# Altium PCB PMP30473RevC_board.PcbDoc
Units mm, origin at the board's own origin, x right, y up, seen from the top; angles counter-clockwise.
Board outline 38.1 x 50.8 mm, 2 copper layers (Top Layer, Bottom Layer), stack 1.575 mm thick; 60 components, 22 nets, 134 pads, 14 vias.
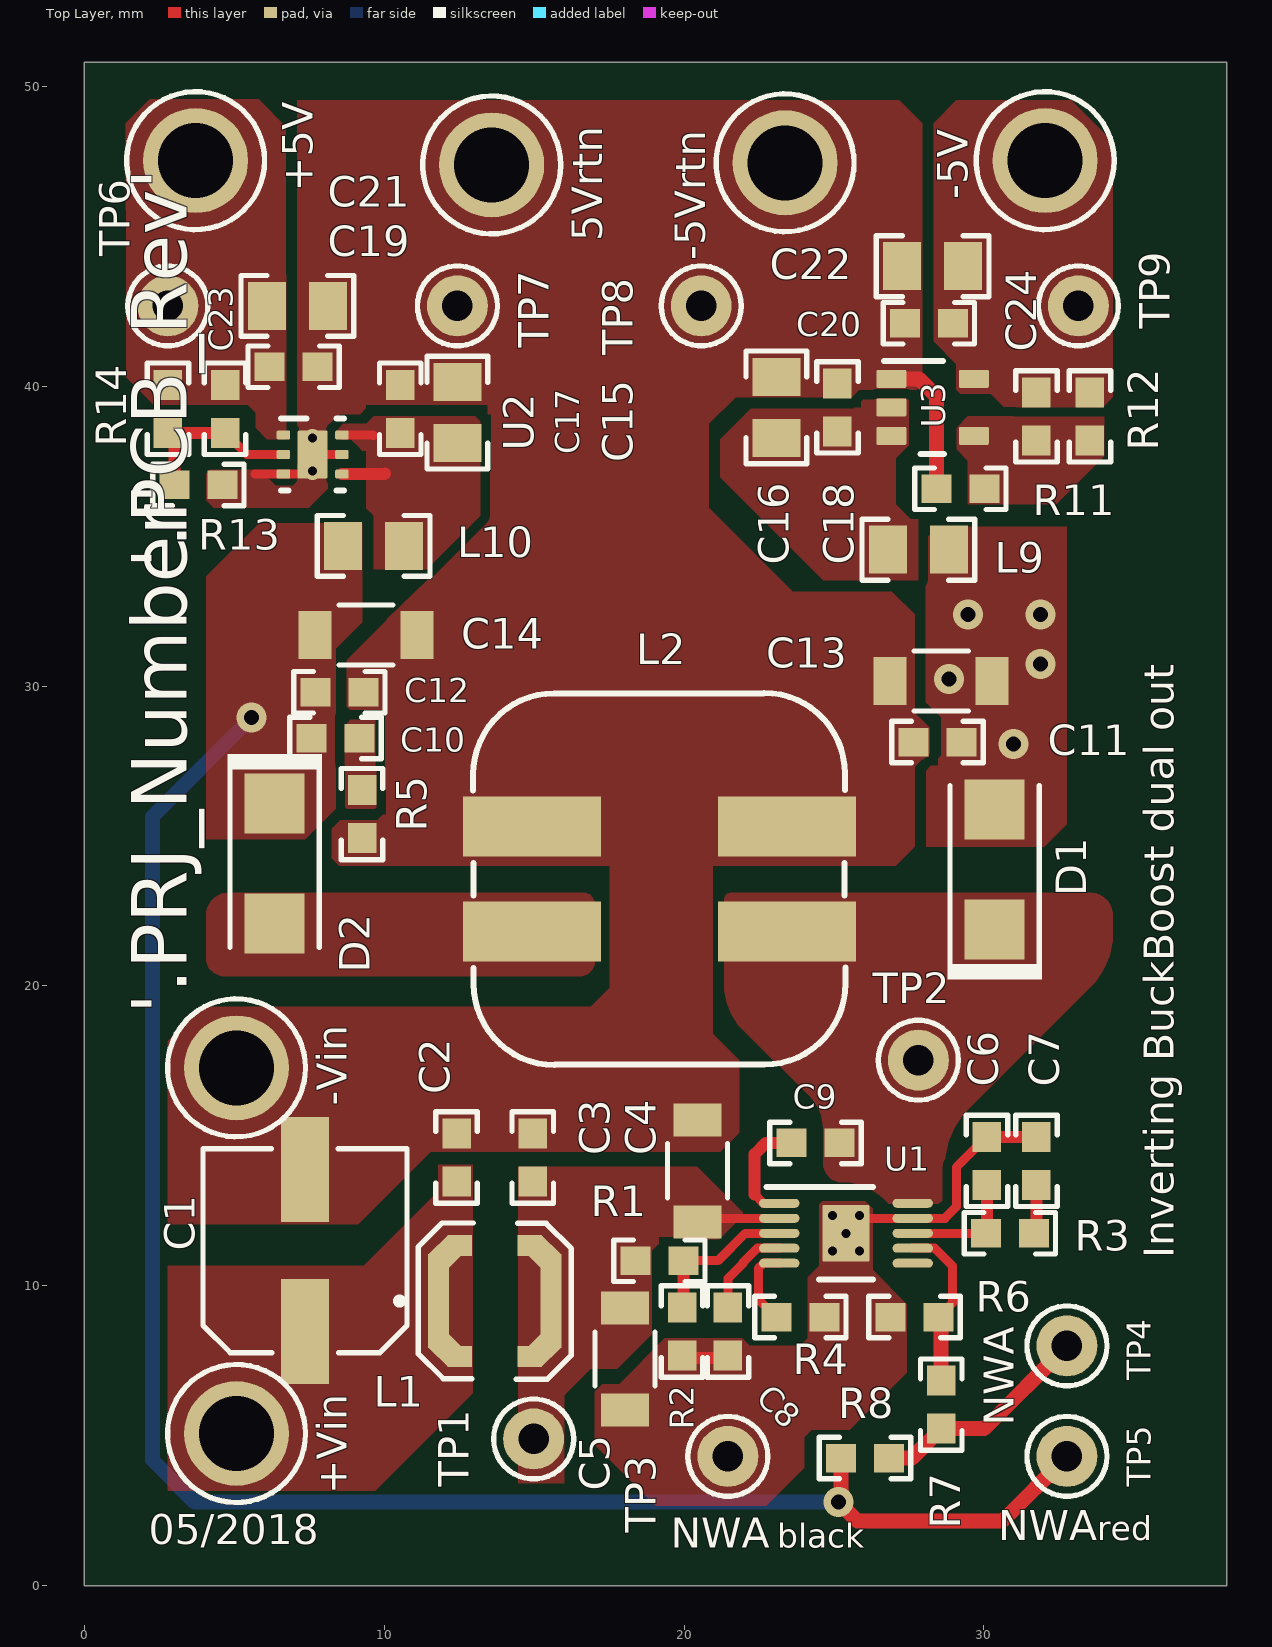
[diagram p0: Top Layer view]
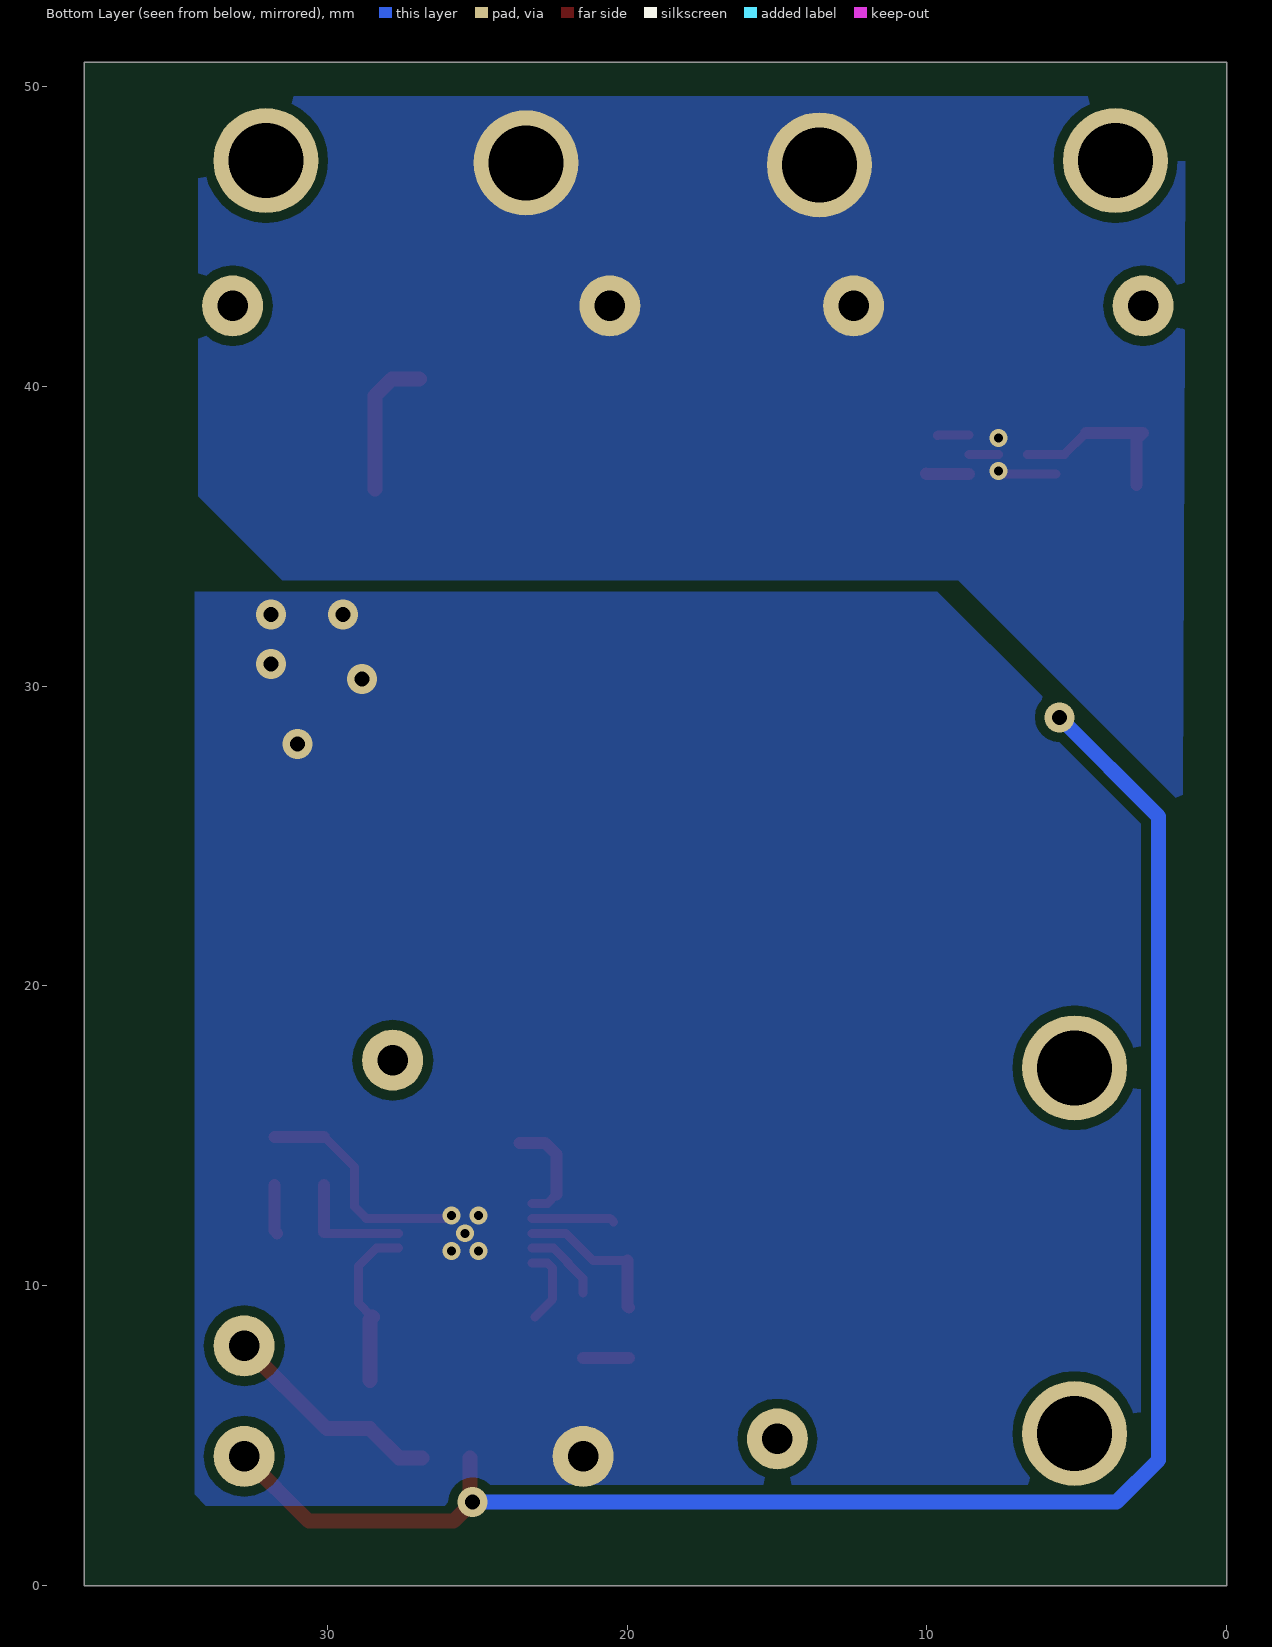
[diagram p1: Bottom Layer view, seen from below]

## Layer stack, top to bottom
Top Solder: solder mask 0.0102, Solder Resist, Dk 3.5
Top Layer: signal copper 0.0356
Dielectric1: core 1.5037, FR-4, Dk 4.8
Bottom Layer: signal copper 0.0356
Bottom Solder: solder mask 0.0102, Solder Resist, Dk 3.5

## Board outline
0,0 0,50.8 38.1,50.8 38.1,0

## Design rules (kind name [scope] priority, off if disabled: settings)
AcuteAngle [All] p1: minimum=4.50000000000000E+0001 checktracksonly=FALSE
AssemblyTestPointUsage [All] p1: valid=2
BoardOutlineClearance BoardOutlineClearance_MountingHoles [OnCopper and InComponentClass('Mounting Holes')] p1: gap=1.016 ignorepadtopadclearanceinfootprint=FALSE
BoardOutlineClearance BoardOutlineClearance_Poly [OnCopper and IsPoly] p2: gap=0.635 ignorepadtopadclearanceinfootprint=FALSE
BoardOutlineClearance [OnCopper and Not InComponentClass('Logo') and not InComponentClass('FiducialMark') and not InRegion(1000,500,4000,800) and not InPoly] p3: gap=1.5 ignorepadtopadclearanceinfootprint=FALSE
Clearance Clearance_Keepouts [((IsTrack Or IsArc) And Not InPoly) And IsFree and IsKeepOut vs ((IsTrack Or IsArc) And Not InPoly) And IsFree and IsKeepOut] p1: gap=0 ignorepadtopadclearanceinfootprint=FALSE
Clearance Clearance_Poly [InPolygon] p2: gap=0.32 ignorepadtopadclearanceinfootprint=FALSE except(0: Arc-Hole Track-Hole SMDPad-Hole THPad-Hole Via-Hole Fill-Hole Poly-Hole Region-Hole Text-Hole)
Clearance Clearance_FiducialMark [IsKeepOut and InComponentClass('FiducialMark') vs IsPad and InComponentClass('FiducialMark')] p3: gap=0 ignorepadtopadclearanceinfootprint=FALSE
Clearance [All] p4: gap=0.2 ignorepadtopadclearanceinfootprint=FALSE except(0: Arc-Hole Track-Hole SMDPad-Hole THPad-Hole Via-Hole Fill-Hole Poly-Hole Region-Hole Text-Hole)
ComponentClearance ComponentClearance_MountingHoles_FiducialMarks [InComponentClass('Mounting Holes') vs InComponentClass('FiducialMark')] p1: gap=1.27 collisioncheckmode=3 verticalgap=0.254 showdistances=FALSE
ComponentClearance ComponentClearance_Shunt [InComponentClass('Header') vs InComponentClass('Shunt')] p2: gap=0 collisioncheckmode=3 verticalgap=0 showdistances=FALSE
ComponentClearance ComponentClearance_Logo [InComponentClass('Logo')] p3: gap=1.27 collisioncheckmode=3 verticalgap=0.254 showdistances=FALSE
ComponentClearance ComponentClearance_ScrewToNut [(HasFootprint('NY PMS 440 0025 PH')) vs (HasFootprint('Keystone_1902C'))] p4: gap=0.127 collisioncheckmode=3 verticalgap=0.254 showdistances=FALSE
ComponentClearance ComponentClearance_MountingHoles [InComponentClass('Mounting Holes')] p5: gap=6.35 collisioncheckmode=3 verticalgap=2540 showdistances=FALSE
ComponentClearance ComponentClearance_SmallPassives [HasFootprint('0201*') or HasFootprint('0402*') or HasFootprint('0508') or HasFootprint('0603*') or HasFootprint('0612') or HasFootprint('0805*') or HasFootprint('0815*') or HasFootprint('0830*') or HasFootprint('1206*') or HasFootprint('1210*') or HasFootprint('1808*') or HasFootprint('1812*') or HasFootprint('1825*') or HasFootprint('2010*') or HasFootprint('2220*') or HasFootprint('2225*') or HasFootprint('2512*') or HasFootprint('2728*') or HasFootprint('3518*') vs HasFootprint('0201*') or HasFootprint('0402*') or HasFootprint('0508') or HasFootprint('0603*') or HasFootprint('0612') or HasFootprint('0805*') or HasFootprint('0815*') or HasFootprint('0830*') or HasFootprint('1206*') or HasFootprint('1210*') or HasFootprint('1808*') or HasFootprint('1812*') or HasFootprint('1825*') or HasFootprint('2010*') or HasFootprint('2220*') or HasFootprint('2225*') or HasFootprint('2512*') or HasFootprint('2728*') or HasFootprint('3518*')] p6: gap=0.38 collisioncheckmode=3 verticalgap=0.254 showdistances=FALSE
ComponentClearance ComponentClearance_THtoSMT [IsThruComponent vs IsSMTComponent] p7: gap=1.016 collisioncheckmode=3 verticalgap=0.762 showdistances=FALSE
ComponentClearance ComponentClearance_THtoTH [IsThruComponent vs IsThruComponent] p8: gap=0.762 collisioncheckmode=3 verticalgap=0.762 showdistances=FALSE
ComponentClearance [All] p9: gap=0.762 collisioncheckmode=3 verticalgap=0.254 showdistances=FALSE
DiffPairsRouting [All] p1: maxlimit=2.54 minlimit=0.254 mostfreqgap=0.254 toplayer_minwidth=0.381 toplayer_maxwidth=0.381 toplayer_prefwidth=0.381 bottomlayer_minwidth=0.381 bottomlayer_maxwidth=0.381 bottomlayer_prefwidth=0.381 maxuncoupledlength=25.4
FabricationTestPointUsage TestPointUsage [All] p1: valid=2 allowmultiple=FALSE
FabricationTestpoint Testpoint [All] p1: side=3 testpointundercomponent=TRUE minsize=1.016 maxsize=2.54 preferedsize=1.524 minholesize=0 maxholesize=1.016 preferedholesize=0.813 testpointgrid=0.025 allowsidetop=TRUE allowsidebottom=TRUE usegrid=TRUE gridtolerance=0
FanoutControl Fanout_LCC [IsLCC] p1: bgadir=Out bgaviamode=Centered fanoutstyle=Auto fanoutdirection=Alternating viagrid=0.025 // Fanout_LCC (Default Rule)
FanoutControl Fanout_BGA [IsBGA] p2: bgadir=Out bgaviamode=Centered fanoutstyle=Auto fanoutdirection=Alternating viagrid=0.025 // Fanout_BGA (Default Rule)
FanoutControl Fanout_Default [All] p4: bgadir=Out bgaviamode=Centered fanoutstyle=Auto fanoutdirection=Alternating viagrid=0.025 // Fanout_Default (Default Rule)
FanoutControl Fanout_Small [(CompPinCount < 5)] p5: bgadir=Out bgaviamode=Centered fanoutstyle=Auto fanoutdirection=OutThenIn viagrid=0.025 // Fanout_Small (Default Rule)
HoleSize [All] p1: absolutevalues=TRUE maxlimit=6.375 minlimit=0.3 maxpercent=80.000 minpercent=20.000
MinimumAnnularRing MinimumAnnularRing_ThermalPadVias [IsVia and InAnyComponent] p1: minimumring=0.15
MinimumAnnularRing [All] p2: minimumring=0.203
MinimumSolderMaskSliver MinimumSolderMaskSliver_Logo [InComponentClass('Logo') vs InComponentClass('Logo')] p1: minsoldermaskwidth=0.018
MinimumSolderMaskSliver [All] p2: minsoldermaskwidth=0.1
PlaneConnect [All] p1: planeconnectstyle=Relief reliefexpansion=0.254 reliefentries=4 reliefconductorwidth=0.254 reliefairgap=0.254
PolygonConnect [All] p1: connectstyle=Direct reliefconductorwidth=0.254 reliefentries=4 polygonreliefangle="90 Angle" airgapwidth=0.254
RoutingVias ThermalPadVias [IsVia and InAnyComponent] p1: holewidth=0.3 width=0.7 viastyle="Through Hole" minholewidth=0.3 minwidth=0.6 maxholewidth=0.6 maxwidth=1.6
RoutingVias [All] p2: holewidth=0.3 width=0.7 viastyle="Through Hole" minholewidth=0.3 minwidth=0.6 maxholewidth=1.016 maxwidth=2
SilkToBoardRegionClearance [Not ((IsComment or IsDesignator) And (Hide <> 'False')) and not InRegion(1000,500,4000,800)] p1:
SilkToSilkClearance SilkToSilkClearance_Pb-FreeLogo [(HasFootprint('Pb-Free_Overlay_Medium') OR HasFootprint('Pb-Free_Overlay_Small')) vs (HasFootprint('Pb-Free_Overlay_Medium') OR HasFootprint('Pb-Free_Overlay_Small'))] p1: silktosilkclearance=0
SilkToSilkClearance [All] p2: silktosilkclearance=0.102
SilkToSolderMaskClearance SilkToComponentPadClearance [(IsPad or IsFill or IsRegion) and InAnycomponent] p1: minsilkscreentomaskgap=0.127 clearancetoexposedcopper=TRUE
SilkToSolderMaskClearance "Silk to Solder Mask Opening" [All] p2: minsilkscreentomaskgap=0.102 clearancetoexposedcopper=FALSE
SolderMaskExpansion [All] p1: expansion=0.05
Width [All] p1: maxlimit=2.54 minlimit=0.152 preferedwidth=0.254 checkconnectedcopper=TRUE
15 further rules are at their usual default settings.

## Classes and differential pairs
component class PMP30473RevC: 5Vrtn +5V +Vin -5V -5Vrtn -Vin C1 C2 C3 C4 C5 C6 C7 C8 C9 C10 C11 C12 C13 C14 C15 C16 C17 C18 C19 C20 C21 C22 D1 D2 L1 L2 L9 L10 R1 R2 R3 R4 R5 R6 R7 R8 R11 R12 TP1 TP2 TP3 TP4 TP5 TP6 TP7 TP8 TP9 U1 U2 U3

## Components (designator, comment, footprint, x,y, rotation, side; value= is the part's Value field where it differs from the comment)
5Vrtn "Suggest using a net name here" Keystone1502-2 13.589,47.371 r270 top
+5V "Suggest using a net name here" Keystone1502-2 3.717,47.515 r0 top
+Vin "Suggest using a net name here" Keystone1502-2 5.08,5.08 r270 top
-5V "Suggest using a net name here" Keystone1502-2 32.038,47.515 r90 top
-5Vrtn "Suggest using a net name here" Keystone1502-2 23.369,47.443 r90 top
-Vin "Suggest using a net name here" Keystone1502-2 5.08,17.272 r270 top
C1 "EEHZC1H330XP" SM_RADIAL_6.3BMM 7.366,11.176 r90 top value=33uF
C2 "GRM188R71H104KA93D" 0603 12.421,14.284 r90 top value=0.1uF
C3 "GRM188R71H104KA93D" 0603 14.961,14.284 r90 top value=0.1uF
C4 "GRM31CR71H475KA12L" 1206_180 20.447,13.839 r90 top value=4.7uF
C5 "GRM31CR72A225KA73L" 1206_190 18.034,7.566 r270 top value=2.2uF
C6 "GRM188R71H471KA01D" 0603 30.099,14.17 r90 top value=470pF
C7 "GRM188R71E683KA01D" 0603 31.75,14.17 r90 top value=0.068uF
C8 "GRM188R71E333KA01D" 0603 21.463,8.48 r270 top value=0.033uF
C9 "GRM188R71E104KA01D" 0603 24.384,14.772 r180 top value=0.1uF
C10 "GRM188R72A471KA01D" 0603 8.382,28.267 r0 top value=470pF
C11 "GRM188R71H104KA93D" 0603 28.448,28.132 r0 top value=0.1uF
C12 "GRM188R71H104KA93D" 0603 8.509,29.791 r0 top value=0.1uF
C13 "GRM31CR71A226KE15L" 1206_180 28.575,30.172 r0 top value=22uF
C14 "GRM31CR71A226KE15L" 1206_180 9.398,31.696 r0 top value=22uF
C15 "GRM21BR71A106KE51K" 0805_HV 12.446,39.116 r90 top value=10uF
C16 "GRM21BR71A106KE51K" 0805_HV 23.081,39.29 r270 top value=10uF
C17 "GRM188R71H104KA93D" 0603 10.541,39.243 r90 top value=0.1uF
C18 "GRM188R71H104KA93D" 0603 25.113,39.29 r270 top value=0.1uF
C19 "GRM188R71H104KA93D" 0603 6.985,40.64 r0 top value=0.1uF
C20 "GRM188R71H104KA93D" 0603 28.161,42.092 r0 top value=0.1uF
C21 "GRM21BR71A106KE51K" 0805_HV 7.112,42.672 r0 top value=10uF
C22 "GRM21BR71A106KE51K" 0805_HV 28.288,43.997 r0 top value=10uF
C23 "GRM188R71E102KA01D" 0603 4.699,39.243 r270 top value=1000pF
C24 "GRM188R71E102KA01D" 0603 31.75,38.989 r270 top value=1000pF
D1 "B180-13-F" SMA 30.353,23.876 r90 top value=80V
D2 "B180-13-F" SMA 6.35,24.076 r270 top value=80V
L1 "LPS4012-332MLB" LPS4012 13.691,9.496 r0 top value=3.3uH
L2 "MSD1260-563ML" MSD1260 19.177,23.568 r180 top value=56uH
L9 "LQM21PN2R2MGS" 0805_HV 27.813,34.544 r180 top value=2.2uH
L10 "LQM21PN2R2MGS" 0805_HV 9.652,34.671 r0 top value=2.2uH
R1 "CRCW0603150KFKEA" 0603 19.177,10.842 r180 top value=150k
R2 "CRCW060349K9FKEA" 0603 19.939,8.48 r90 top value=49.9k
R3 "CRCW06037K15FKEA" 0603 30.861,11.757 r180 top value=7.15k
R4 "CRCW0603412KFKEA" 0603 23.876,8.963 r180 top value=412k
R5 "CRCW0603100RJNEA" 0603 9.271,25.727 r90 top value=100
R6 "CRCW06032K00FKEA" 0603 27.686,8.963 r180 top value=2.00k
R7 "CRCW060325K5FKEA" 0603 28.575,6.042 r270 top value=25.5k
R8 "CRCW060349R9FKEA" 0603 26.035,4.264 r0 top value=49.9
R11 "CRCW060323K7FKEA" 0603 29.21,36.576 r180 top value=23.7k
R12 "CRCW060376K8FKEA" 0603 33.528,38.989 r270 top value=76.8k
R13 "CRCW060323K7FKEA" 0603 3.81,36.703 r180 top value=23.7k
R14 "CRCW060376K8FKEA" 0603 2.794,39.243 r270 top value=76.8k
TP1 "5000" Keystone5000 14.986,4.899 r90 top value=Red
TP2 "5002" Keystone5002 27.813,17.526 r180 top
TP3 "5117" Keystone5117 21.463,4.318 r180 top value=Blue
TP4 "5003" Keystone5003 32.766,8.001 r90 top value=Orange
TP5 "5000" Keystone5000 32.766,4.318 r90 top value=Red
TP6 "5000" Keystone5000 2.794,42.672 r0 top value=Red
TP7 "5001" Keystone5001 12.446,42.672 r0 top
TP8 "5001" Keystone5001 20.574,42.672 r180 top
TP9 "5117" Keystone5117 33.147,42.672 r180 top value=Blue
U1 "TPS57160QDGQRQ1" DGQ0010D_N 25.4,11.757 r0 top
U2 "TPS79901QDRVRQ1" DRV0006A 7.62,37.719 r0 top
U3 "TPS72301QDBVRQ1" DBV0005A_N 28.288,39.29 r0 top

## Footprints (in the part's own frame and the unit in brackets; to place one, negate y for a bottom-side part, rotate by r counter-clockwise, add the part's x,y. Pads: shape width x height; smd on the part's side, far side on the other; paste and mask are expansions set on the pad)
0603 [mm] "0603 from SM-752 data"
  rect 1x0.95 smd: 1(-0.8,0) 2(0.8,0)
  silkscreen extent -1.52,-0.69 1.52,0.69, body extent -0.87,-0.47 0.87,0.47, height 1
0805_HV [mil] "0805 with 30mil clearance between pads"
  rect 50x63 smd: 1(-40,0) 2(40,0)
  silkscreen extent -74,-40 74,40, body extent -43,-29 43,29, height 57
1206_180 [mm] "1206_180"
  rect 1.1x1.6 smd: 1(-1.7,0) 2(1.7,0)
  silkscreen extent -0.9,-1 0.9,1, body extent -1.75,-0.95 1.75,0.95, height 1.8
1206_190 [mm] "1206_190"
  rect 1.1x1.6 smd: 1(-1.7,0) 2(1.7,0)
  silkscreen extent -0.9,-1 0.9,1, body extent -1.75,-0.95 1.75,0.95, height 1.9
DBV0005A_N [mm] "SOT23, 5-Leads, Body 2.9x1.6mm, Pitch 0.95mm, Lead Span 2.8mm, IPC Medium Density"
  rrect17% 1x0.6 smd: 1(-1.375,0.95) 2(-1.375,0) 3(-1.375,-0.95) 4(1.375,-0.95) 5(1.375,0.95)
  silkscreen extent -1.63,-1.55 0.38,1.55, body extent -1.42,-1.46 1.42,1.46, height 1.09
DGQ0010D_N [mm] "TSSOP, 10-Leads, Body 3x3mm, Pitch 0.5mm, Thermal Pad 1.88x1.57mm, IPC Medium Density"
  rrect100% 1.35x0.3 smd: 1(-2.225,1) 2(-2.225,0.5) 3(-2.225,0) 4(-2.225,-0.5) 5(-2.225,-1) 6(2.225,-1) 7(2.225,-0.5) 8(2.225,0) 9(2.225,0.5) 10(2.225,1)
  rrect6% 1.57x1.88 smd: 11(0,0)
  silkscreen extent -2.65,-1.55 0.9,1.55, body extent -2.46,-1.5 2.46,1.5, height 1.1
DRV0006A [mm] "SON, 6-Leads, Body 2x2mm, Pitch 0.65mm, Thermal Pad 1.6x1mm, TI Recommended"
  rrect33% 0.45x0.3 smd: 1(-0.975,0.65) 2(-0.975,0) 3(-0.975,-0.65) 4(0.975,-0.65) 5(0.975,0) 6(0.975,0.65)
  rrect14% 1x0.7 on Top Paste: 7(0,-0.45) 7(0,0.45)
  rrect10% 1x1.6 smd paste-0.5: 7(0,0)
  silkscreen extent -1.05,-1.2 1.05,1.2, body extent -1.05,-1.05 1.05,1.05, height 0.81
Keystone1502-2 [mm] "Double Turret"
  round 3.5 hole 2.5: 1(0,0)
  silkscreen extent -2.3,-2.3 2.3,2.3, body extent -1.6,-1.6 1.59,1.6, height 5.62
Keystone5000 [mil] "For Keystone 500x miniature loop terminals"
  round 80 hole 40: 1(0,0)
  silkscreen extent -52,-52 52,52, body extent -49,-49 49,49, height 182
Keystone5001 [mil] "For Keystone 500x miniature loop terminals"
  round 80 hole 40: 1(0,0)
  silkscreen extent -52,-52 52,52, body extent -49,-49 49,49, height 182
Keystone5002 [mil] "For Keystone 500x miniature loop terminals"
  round 80 hole 40: 1(0,0)
  silkscreen extent -52,-52 52,52, body extent -49,-49 49,49, height 182
Keystone5003 [mil] "For Keystone 500x miniature loop terminals"
  round 80 hole 40: 1(0,0)
  silkscreen extent -52,-52 52,52, body extent -49,-49 49,49, height 182
Keystone5117 [mil] "For Keystone 500x miniature loop terminals"
  round 80 hole 40: 1(0,0)
  silkscreen extent -52,-52 52,52, body extent -49,-49 49,49, height 182
LPS4012 [mm] "Coilcraft recommended land pattern.  Document 433-2, rev 10/20/08"
  rect 0.7x3.124 smd: 1(-1.881,0) 2(1.881,0)
  rect 0.902x0.801 smd rot 135: 1(-1.592,-1.605) 2(1.592,1.605)
  rect 0.902x0.801 smd rot 45: 1(-1.592,1.605) 2(1.592,-1.605)
  rect 0.812x0.7 smd: 1(-1.168,-1.85) 1(-1.168,1.85) 2(1.168,-1.85) 2(1.168,1.85)
  silkscreen extent -3.26,-2.6 2.55,2.6, body extent -2.05,-2.05 2.05,2.05, height 1.22
MSD1260 [mm] "COILCRAFT"
  rect 4.6x2 smd mask+0.051: 1(-4.25,1.753) 2(-4.25,-1.753) 3(4.25,-1.753) 4(4.25,1.753)
  silkscreen extent -6.21,-6.21 6.21,6.21, body extent -6.1,-6.1 6.1,6.1, height 6
SM_RADIAL_6.3BMM [mm] "Nichicon 6.3x7.7"
  rect 3.5x1.6 smd: 1(-2.7,0) 2(2.7,0)
  silkscreen extent -3.4,-3.4 3.4,3.4, body extent -3.4,-3.4 3.4,3.4, height 8
SMA [mm] "Molded Diode, 2-Leads, Body 4.3x2.6mm, IPC Medium Density, based on OnSemi component dimensions and land pattern"
  rect 2x2 smd: 1(-2,0) 2(2,0)
  silkscreen extent -3.66,-1.57 2.79,1.57, body extent -2.6,-1.3 2.6,1.3, height 2.42

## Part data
5Vrtn +5V +Vin -5V -5Vrtn -Vin: library part 1502-2, "Terminal, Turret, TH, Double", Manufacturer=Keystone, Supplier Part Number 1=36-1502-2-ND
C1: "CAP, Polymer Hybrid, 33 µF, 50 V,+/- 20%, 40 ohm, 6.3x7.7 SMD", Manufacturer=Panasonic, Supplier Part Number 1=P15464CT-ND, Tolerance_%=20, Value1="40 ohm", Value2=50V, ValueDisplayed=33µF
C2 C3: "CAP, CERM, 0.1 µF, 50 V,+/- 10%, X7R, 0603", Cap_Case=0603, Manufacturer=MuRata, Supplier Part Number 1=490-1519-1-ND, TempCo=X7R, Tolerance_%=10, Value2=50V, ValueDisplayed=0.1µF
C4: "CAP, CERM, 4.7 µF, 50 V,+/- 10%, X7R, 1206", Cap_Case=1206, Manufacturer=MuRata, Supplier Part Number 1=24R6347, TempCo=X7R, Tolerance_%=10, Value2=50V, ValueDisplayed=4.7µF
C5: "CAP, CERM, 2.2 µF, 100 V,+/- 10%, X7R, 1206", Cap_Case=1206, Manufacturer=MuRata, Supplier Part Number 1=490-7209-1-ND, TempCo=X7R, Tolerance_%=10, Value2=100V, ValueDisplayed=2.2µF
C6: "CAP, CERM, 470 pF, 50 V,+/- 10%, X7R, 0603", Cap_Case=0603, Manufacturer=MuRata, Supplier Part Number 1=490-1489-1-ND, TempCo=X7R, Tolerance_%=10, Value2=50V, ValueDisplayed=470pF
C7: "CAP, CERM, 0.068 µF, 25 V,+/- 10%, X7R, 0603", Cap_Case=0603, Manufacturer=MuRata, Supplier Part Number 1=490-1523-1-ND, TempCo=X7R, Tolerance_%=10, Value2=25V, ValueDisplayed=0.068µF
C8: "CAP, CERM, 0.033 µF, 25 V, +/- 10%, X7R, 0603", Cap_Case=0603, Manufacturer=MuRata, Supplier Part Number 1=490-1521-1-ND, TempCo=X7R, Tolerance_%=10, Value1=Unknown, Value2=25V, ValueDisplayed=33nF
C9: "CAP, CERM, 0.1 µF, 25 V, +/- 10%, X7R, 0603", Cap_Case=0603, Manufacturer=MuRata, Supplier Part Number 1=490-1524-1-ND, TempCo=X7R, Tolerance_%=10, Value1=Unknown, Value2=25V, ValueDisplayed=0.1µF
C10: "CAP, CERM, 470 pF, 100 V,+/- 10%, X7R, 0603", Cap_Case=0603, Manufacturer=MuRata, Supplier Part Number 1=490-1467-1-ND, TempCo=X7R, Tolerance_%=10, Value2=100V, ValueDisplayed=470pF
C11 C12 C17 C18 C19 C20: "CAP, CERM, 0.1 µF, 50 V, +/- 10%, X7R, 0603", Cap_Case=0603, Manufacturer=MuRata, Supplier Part Number 1=490-1519-1-ND, TempCo=X7R, Tolerance_%=10, Value1=Unknown, Value2=50V, ValueDisplayed=0.1µF
C13 C14: "CAP, CERM, 22 µF, 10 V,+/- 10%, X7R, 1206", Cap_Case=1206, Manufacturer=MuRata, Supplier Part Number 1=490-5309-1-ND, TempCo=X7R, Tolerance_%=10, Value2=10V, ValueDisplayed=22µF
C15 C16 C21 C22: "CAP, CERM, 10 µF, 10 V,+/- 10%, X7R, 0805", Cap_Case=0805, Manufacturer=MuRata, Supplier Part Number 1=490-6477-1-ND, TempCo=X7R, Tolerance_%=10, Value2=10V, ValueDisplayed=10µF
C23 C24: "CAP, CERM, 1000 pF, 25 V,+/- 10%, X7R, 0603", Cap_Case=0603, Manufacturer=MuRata, Supplier Part Number 1=GRM188R71E102KA01D-ND, TempCo=X7R, Tolerance_%=10, Value2=25V, ValueDisplayed=1000pF
D1 D2: "Diode, Schottky, 80 V, 1 A, SMA", Manufacturer="Diodes Inc.", Supplier Part Number 1=B180-FDICT-ND, Value1=1A, Value2=0.79V
L1: "Inductor, Shielded Drum Core, Ferrite, 3.3 µH, 1.4 A, 0.1 ohm, SMD", Manufacturer=Coilcraft, Value1="0.1 ohm", Value2=1.4A, ValueDisplayed=3.3µH
L2: "Coupled inductor, 56 µH, 3.07 A, 0.198 ohm, AEC-Q200 Grade 3, TH", Manufacturer=Coilcraft, ValueDisplayed=56µH
L9 L10: "Inductor, Multilayer, Ferrite, 2.2 µH, 0.95 A, 0.18 ohm, SMD", Manufacturer=MuRata, Supplier Part Number 1=LQM21PN2R2MGSD-ND, Value1="0.18 ohm", Value2=0.95A, ValueDisplayed=2.2µH
R1: "RES, 150 k, 1%, 0.1 W, 0603", Manufacturer=Vishay-Dale, Power_W=0.1, Supplier Part Number 1=541-150KHCT-ND, TempCo="100 ppm/C", Tolerance_%=1, Value1=1%, Value2=0.1W, Value_Code=150k
R2: "RES, 49.9 k, 1%, 0.1 W, 0603", Manufacturer=Vishay-Dale, Power_W=0.1, Supplier Part Number 1=541-49.9KHCT-ND, TempCo="100 ppm/C", Tolerance_%=1, Value1=1%, Value2=0.1W, Value_Code=49k9, ValueDisplayed=49.9k
R3: "RES, 7.15 k, 1%, 0.1 W, 0603", Manufacturer=Vishay-Dale, Power_W=0.1, Supplier Part Number 1=541-7.15KHCT-ND, TempCo="100 ppm/C", Tolerance_%=1, Value1=1%, Value2=0.1W, Value_Code=7k15, ValueDisplayed=7.15k
R4: "RES, 412 k, 1%, 0.1 W, 0603", Manufacturer=Vishay-Dale, Power_W=0.1, Supplier Part Number 1=541-412KHCT-ND, TempCo="100 ppm/C", Tolerance_%=1, Value1=1%, Value2=0.1W, Value_Code=412k
R5: "RES, 100, 5%, 0.1 W, 0603", Manufacturer=Vishay-Dale, Power_W=0.1, Supplier Part Number 1=541-100GCT-ND, TempCo="200 ppm/C", Tolerance_%=5, Value1=5%, Value2=0.1W, Value_Code=100R, ValueDisplayed=100
R6: "RES, 2.00 k, 1%, 0.1 W, 0603", Manufacturer=Vishay-Dale, Power_W=0.1, Supplier Part Number 1=541-2.00KHCT-ND, TempCo="100 ppm/C", Tolerance_%=1, Value1=1%, Value2=0.1W, Value_Code=2k00, ValueDisplayed=2.00k
R7: "RES, 25.5 k, 1%, 0.1 W, 0603", Manufacturer=Vishay-Dale, Power_W=0.1, Supplier Part Number 1=541-25.5KHCT-ND, TempCo="100 ppm/C", Tolerance_%=1, Value1=1%, Value2=0.1W, Value_Code=25k5, ValueDisplayed=25.5k
R8: "RES, 49.9, 1%, 0.1 W, 0603", Manufacturer=Vishay-Dale, Power_W=0.1, Supplier Part Number 1=541-49.9HCT-ND, TempCo="100 ppm/C", Tolerance_%=1, Value1=1%, Value2=0.1W, Value_Code=49R9, ValueDisplayed=49.9
R11 R13: "RES, 23.7 k, 1%, 0.1 W, 0603", Manufacturer=Vishay-Dale, Power_W=0.1, Supplier Part Number 1=541-23.7KHCT-ND, TempCo="100 ppm/C", Tolerance_%=1, Value1=1%, Value2=0.1W, Value_Code=23k7, ValueDisplayed=23.7k
R12 R14: "RES, 76.8 k, 1%, 0.1 W, 0603", Manufacturer=Vishay-Dale, Power_W=0.1, Supplier Part Number 1=541-76.8KHCT-ND, TempCo="100 ppm/C", Tolerance_%=1, Value1=1%, Value2=0.1W, Value_Code=76k8, ValueDisplayed=76.8k
TP1 TP5 TP6: "Test Point, Miniature, Red, TH", Manufacturer=Keystone, Supplier Part Number 1=5000K-ND
TP2: "Test Point, Miniature, White, TH", Color=White, Manufacturer=Keystone, Supplier Part Number 1=36-5002-ND
TP3 TP9: "Test Point, Miniature, Blue, TH", Color=Blue, Manufacturer=Keystone, Supplier Part Number 1=36-5117-ND
TP4: "Test Point, Miniature, Orange, TH", Manufacturer=Keystone, Supplier Part Number 1=5003K-ND
TP7 TP8: "Test Point, Miniature, Black, TH", Color=Black, Manufacturer=Keystone, Supplier Part Number 1=36-5001-ND
U1: "Automotive 3.5V to 60V, 1.5A Step Down SWIFT(TM) Converter with Eco-Mode(TM), DGQ0010D (VSSOP-10)", Alternate Manufacturer="Texas Instruments"
U2: "Single Output High PSRR LDO, 200 mA, Adjustable 1.2 to 6.5 V Output, 2.7 to 6.5 V Input, with Low IQ, 6-pin SON (DRV), -40 to 125 degC, Green (RoHS & no Sb/Br)", Alternate Manufacturer="Texas Instruments", Alternate PartNumber=Equivalent, Rating=Automotive, Supplier Part Number 1=296-23872-2-ND
U3: "Single Output High PSRR LDO, 200 mA, Adjustable -10 to -1.2 V Output, -10 to -2.7 V Input, 5-pin SOT-23 (DBV), -40 to 125 degC, Green (RoHS & no Sb/Br)", Alternate Manufacturer="Texas Instruments", Alternate PartNumber=Equivalent, Supplier Part Number 1=TPS72301QDBVRQ1-ND

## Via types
v1: diameter 0.6, hole 0.3, Top Layer to Bottom Layer, 7 vias
v2: diameter 1, hole 0.5, Top Layer to Bottom Layer, 6 vias
v3: diameter 1, hole 0.5, Top Layer to Bottom Layer, tented top, 1 vias

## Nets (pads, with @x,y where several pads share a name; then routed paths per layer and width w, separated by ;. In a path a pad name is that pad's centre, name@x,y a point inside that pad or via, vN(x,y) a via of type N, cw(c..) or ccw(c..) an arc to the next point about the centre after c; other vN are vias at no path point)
+5V5: C10.1 C12.1 C14.1 D2.1 L10.1 R8.1 TP5.1 | length 59.9
  Top Layer w0.5: R8.1 25.235,2.883 v2(25.146,2.794) 25.781,2.159 30.607,2.159 TP5.1
  Bottom Layer w0.5: v2(5.588,28.956) 2.286,25.654 2.286,4.191 3.683,2.794 v2(25.146,2.794)
GND: 5Vrtn.1 -5Vrtn.1 -Vin.1 C1.2 C2.2 C3.2 C4.2 C11.1 C12.2 C13.1 C14.2 C15.2 C16.1 C17.2 C18.1 C19.2 C20.1 C21.2 C22.1 L2.2 L2.3 R5.1 R11.2 R13.1 TP7.1 TP8.1 U2.3 U2.5 U2.7@7.62,37.719 U3.1 | length 7.6
  Top Layer w0.3: 5.7,37.069 U2.3 U2.7@7.52,37.069 ; U2.7@7.62,37.719 U2.5
  Top Layer w0.5: U3.1 27.838,40.24 28.41,39.668 R11.2
  other v1: 7.62,37.169 7.62,38.269
Net+5V_1: +5V.1 C19.1 C21.1 C23.1 R14.1 TP6.1 U2.1
Net+Vin_1: +Vin.1 C1.1 C2.1 L1.1
Net-5V_1: -5V.1 C20.2 C22.2 C24.1 R12.1 TP9.1 U3.5
NetC3_1: C3.1 C4.1 C5.1 L1.2 R1.2 TP1.1 U1.2 | length 2.8
  Top Layer w0.3: C4.1 20.564,12.257 U1.2
NetC5_2: C5.2 C6.2 C7.2 C8.2 C11.2 C13.2 D1.2 L9.1 R2.1 R4.1 R6.2 TP3.1 U1.9 U1.11 | length 9.3
  Top Layer w0.3: U1.11@25.9,12.257 U1.9 28.694,12.257 29.083,12.646 29.083,13.954 C6.2
  Top Layer w0.4: R2.1@19.939,7.605 C8.2@21.463,7.605 ; C6.2 C7.2
  other v1: 24.95,11.157 25.85,11.157 25.4,11.757 24.95,12.357 25.85,12.357
  other v2: 30.988,28.067 31.877,30.734 29.464,32.385 31.877,32.385
  other v3: 28.829,30.226
NetC6_1: C6.1 R3.2 U1.8 | length 4
  Top Layer w0.3: U1.8 R3.2
  Top Layer w0.4: R3.2@30.099,11.795 C6.1
NetC7_1: C7.1 R3.1 | length 1.6
  Top Layer w0.4: R3.1 31.75,11.846 C7.1
NetC8_1: C8.1 U1.4 | length 2.6
  Top Layer w0.3: C8.1@21.463,9.763 21.463,10.244 21.97,10.751 21.97,10.784 22.443,11.257 U1.4
NetC9_1: C9.1 D1.1 L2.1 TP2.1 U1.10
NetC9_2: C9.2 U1.1 | length 3.7
  Top Layer w0.3: 22.352,13.052 22.647,12.757 U1.1
  Top Layer w0.4: 22.352,13.052 22.352,14.391 22.733,14.772 C9.2
NetC10_2: C10.2 R5.2
NetC15_1: C15.1 C17.1 L10.2 U2.4 U2.6 | length 2.5
  Top Layer w0.3: U2.6 9.637,38.369 9.652,38.354
  Top Layer w0.4: U2.4 10.018,37.069 10.033,37.084
NetC16_2: C16.2 C18.2 L9.2 U3.2 U3.3
NetC23_2: C23.2 R13.2 R14.2 U2.2 | length 6
  Top Layer w0.3: C23.2 5.423,37.719 U2.2
  Top Layer w0.4: R13.2 3.01,38.227 R14.2 C23.2
NetC24_2: C24.2 R11.1 R12.2 U3.4
NetD2_2: D2.2 L2.4
NetR1_1: R1.1 R2.2 U1.3 | length 5.2
  Top Layer w0.3: R1.1 21.133,10.842 22.047,11.757 U1.3
  Top Layer w0.4: R2.2 19.977,9.318 R1.1
NetR4_2: R4.2 U1.5 | length 2.6
  Top Layer w0.3: R4.2 22.479,9.56 22.479,10.586 22.65,10.757 U1.5
NetR6_1: R6.1 R7.1 U1.7 | length 5.6
  Top Layer w0.3: U1.7 28.357,11.257 28.956,10.658 28.956,9.433 R6.1
  Top Layer w0.5: R6.1 28.575,8.874 R7.1
NetR7_2: R7.2 R8.2 TP4.1 | length 7.5
  Top Layer w0.5: R8.2 27.597,4.264 R7.2 30.007,5.242 TP4.1
pads on no net: U1.6 U2.7@7.62,37.269 U2.7@7.62,38.169

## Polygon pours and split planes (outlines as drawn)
GND on Top Layer "TOP_LAYER_GND_P060" (solid, remove dead copper, pour order 60): 8.128,36.576 7.493,35.941 4.318,35.941 4.064,36.195 4.064,37.084 4.191,37.211 5.842,37.211 6.384,36.669 6.951,36.669 7.112,36.83 7.112,37.465 8.001,37.465 8.128,37.338
GND on Top Layer "TOP_LAYER_GND_P010" (solid, remove dead copper, pour order 10): 2.794,12.065 9.144,12.065 11.557,14.478 21.209,14.478 21.844,15.113 21.844,17.526 20.955,18.415 20.955,26.797 17.399,26.797 17.526,26.67 17.526,19.939 16.891,19.304 3.937,19.304 2.794,18.161
NetC9_1 on Top Layer "TOP_LAYER_NETC9_1_P008" (solid, remove dead copper, pour order 8): 33.528,23.114 cw(c33.528,22.352) 34.29,22.352 34.29,21.753 cw(c31.75,21.753) 33.546,19.957 29.446,15.857 ccw(c31.242,14.061) 28.702,14.061 28.702,12.827 cw(c28.448,12.827) 28.448,12.573 27.096,12.573 cw(c27.096,12.817) 26.923,12.644 26.694,12.873 ccw(c25.273,11.452) 25.273,13.462 cw(c25.273,14.097) 24.638,14.097 24.638,15.247 ccw(c23.121,15.247) 24.194,16.319 21.965,18.548 cw(c23.482,20.066) 21.336,20.066 21.336,22.86 cw(c21.59,22.86) 21.59,23.114
NetD2_2 on Top Layer "TOP_LAYER_NETD2_2_P004" (solid, remove dead copper, pour order 4): 16.51,20.32 ccw(c16.51,20.828) 17.018,20.828 17.018,22.733 ccw(c16.637,22.733) 16.637,23.114 4.826,23.114 ccw(c4.826,22.352) 4.064,22.352 4.064,20.955 ccw(c4.699,20.955) 4.699,20.32
NetC3_1 on Top Layer "TOP_LAYER_NETC3_1_P002" (solid, remove dead copper, pour order 2): 14.478,3.429 14.478,13.962 14.486,13.97 20.447,13.97 21.971,12.446 21.971,12.192 21.336,11.557 19.304,11.557 18.923,11.176 18.923,8.382 17.78,7.239 16.891,7.239 16.002,6.35 16.002,3.429
Net+Vin_1 on Top Layer "TOP_LAYER_NET+VIN_1_P000" (solid, remove dead copper, pour order 0): 2.794,10.668 9.325,10.668 11.811,13.154 11.811,14.043 12.954,14.043 12.954,6.423 9.706,3.175 2.794,3.175
+5V5 on Top Layer "TOP_LAYER_+5V5_P014" (solid, remove dead copper, pour order 14): 4.064,24.892 7.366,24.892 8.382,25.908 8.382,31.242 9.271,32.131 9.271,35.433 5.842,35.433 4.064,33.655
NetC15_1 on Top Layer "TOP_LAYER_NETC15_1_P016" (solid, remove dead copper, pour order 16): 9.398,38.735 8.636,38.735 8.382,38.481 8.636,38.227 8.89,38.227 9.271,37.846 9.398,37.846 9.398,35.93 9.652,35.676 9.652,33.898 11.43,33.898 13.208,35.676 13.208,36.322 13.208,38.825 13.044,38.989 9.652,38.989
Net+5V_1 on Top Layer "TOP_LAYER_NET+5V_1_P018" (solid, remove dead copper, pour order 18): 1.397,42.926 1.397,40.292 2.319,39.37 5.461,39.37 5.715,39.116 5.715,38.608 6.096,38.227 6.731,38.227 6.731,38.769 6.731,48.641 5.817,49.555 2.184,49.555 1.397,48.768
NetC5_2 on Top Layer "TOP_LAYER_NETC5_2_P020" (solid, remove dead copper, pour order 20): 28.067,24.638 32.004,24.638 32.766,25.4 32.766,35.306 28.448,35.306 28.067,34.925 28.067,29.464 28.575,28.956 28.575,27.686 28.067,27.178
NetC24_2 on Top Layer "TOP_LAYER_NETC24_2_P028" (solid, remove dead copper, pour order 28): 29.464,36.068 29.464,37.514 29.087,37.891 29.087,38.612 29.464,38.989 34.003,38.989 34.003,37.66 32.411,36.068
Net-5V_1 on Top Layer "TOP_LAYER_NET-5V_1_P032" (solid, remove dead copper, pour order 32): 30.734,39.243 30.226,39.751 29.21,39.751 29.083,39.878 29.083,40.732 28.321,41.494 28.321,48.768 29.083,49.53 32.908,49.53 34.29,48.148 34.29,39.624 33.909,39.243
GND on Top Layer "TOP_LAYER_GND_P038" (solid, remove dead copper, pour order 38): 10.096,32.194 10.096,32.22 13.462,35.527 13.462,39.37 9.398,39.37 9.398,37.855 7.112,37.855 7.112,49.53 27.178,49.53 27.94,48.768 27.94,40.005 27.813,39.878 25.842,39.878 25.588,39.624 21.717,39.624 20.828,38.735 20.828,35.941 23.622,33.147 26.924,33.147 27.686,32.385 27.686,29.115 28.194,28.607 28.194,27.559 27.94,27.559 27.686,27.305 27.686,24.638 27.051,24.003 8.509,24.003 8.255,24.257 8.255,25.236 8.546,25.527 9.779,25.527 10.033,25.781 10.033,29.083 9.906,29.21 8.869,29.21 8.763,29.316 8.763,30.861
NetC16_2 on Top Layer "TOP_LAYER_NETC16_2_P042" (solid, remove dead copper, pour order 42): 23.114,35.052 24.638,33.528 27.813,33.528 27.813,35.56 27.559,35.56 27.051,36.068 27.051,37.592 27.487,38.028 27.487,39.624 26.035,39.624 25.654,39.243 22.225,39.243 21.209,38.227 21.209,36.957
NetC5_2 on Top Layer "TOP_LAYER_NETC5_2_P048" (solid, remove dead copper, pour order 48): 24.257,5.207 25.527,5.207 27.432,7.112 27.432,9.398 26.289,10.541 26.289,12.573 26.035,12.827 24.615,12.827 24.511,12.723 24.511,10.668 24.13,10.287 24.13,8.255 23.876,8.001 22.192,8.001 21.938,8.255 19.365,8.255 17.841,6.731 17.272,6.731 17.018,6.477 17.018,5.207 17.018,4.699 19.05,2.667 22.733,2.667 24.003,3.937 24.003,4.953
NetC10_2 on Top Layer "TOP_LAYER_NETC10_2_P056" (solid, remove dead copper, pour order 56): 9.906,26.035 9.779,25.908 8.763,25.908 8.636,26.035 8.636,28.829 8.763,28.956 9.652,28.956 9.932,28.676 9.932,28.067
NetC5_2 on Bottom Layer "BOTTOM_LAYER_NETC5_2_P054" (solid, remove dead copper, pour order 54): 2.667,4.191 4.191,2.667 34.036,2.667 34.417,3.048 34.417,33.147 9.652,33.147 2.667,26.162
GND on Bottom Layer "BOTTOM_LAYER_GND_P058" (solid, remove dead copper, pour order 58): 1.481,26.044 8.965,33.528 31.496,33.528 34.29,36.322 34.29,49.657 1.375,49.657

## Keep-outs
Keep-Out Layer:
  text ".Layer_Name" at 14.656,-21.806 h1.52

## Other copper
Top Layer:
  text ".Layer_Name" at 14.656,-21.806 h1.52
Bottom Layer:
  text ".Layer_Name" at 14.656,-21.806 h1.52

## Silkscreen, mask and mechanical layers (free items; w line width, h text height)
Top Overlay:
  text "'.PCB_Rev'" at 3.429,33.909 h1.85 r90
  text "'.PRJ_Number'" at 3.429,19.05 h1.85 r90
  text "Inverting BuckBoost dual out" at 36.322,10.922 h1 r90
  text "NWA" at 30.988,5.334 h1 r90
  text "NWA" at 30.48,1.524 h1
  text "red" at 33.782,1.524 h0.8
  text "05/2018" at 2.159,1.397 h1
  text "NWA" at 19.558,1.27 h1
  text "black" at 23.114,1.27 h0.8
  text ".Layer_Name" at 14.656,-21.806 h1.52
Bottom Overlay:
  text ".Layer_Name" at 14.656,-21.806 h1.52
Top Paste:
  text ".Layer_Name" at 14.656,-21.806 h1.52
Bottom Paste:
  text ".Layer_Name" at 14.656,-21.806 h1.52
Top Solder:
  text ".Layer_Name" at 14.656,-21.806 h1.52
  text ".Layer_Name" at 14.656,-21.806 h1.52
Bottom Solder:
  text "'.PCB_Rev'" at 10.922,37.871 h1.85
  text "'.PRJ_Number'" at 26.086,37.871 h1.85
  text "TPS57160-q1" at 26.035,35.433 h1
  text ".Layer_Name" at 14.656,-21.806 h1.52
Drill Guide:
  text ".Layer_Name" at 14.656,-21.806 h1.52
M1 Board Outline:
  the board outline again, w0.254
  text ".Layer_Name" at 14.656,-21.806 h1.52
M2 Board Dimensions:
  rectangle: 0,-6.985 3.175,-3.81
  rectangle: 3.175,-10.16 12.7,-6.985
  lines w0.178: 0,-6.985 25.4,-6.985 ; 3.175,-10.16 3.175,-3.81 ; 6.35,-10.16 6.35,-3.81 ; 12.7,-10.16 12.7,-3.81 ; 19.05,-10.16 19.05,-3.81 ; 0,-10.16 25.4,-10.16 25.4,-3.81 0,-3.81 0,-10.16
  text "'.Print_Date'" at 0.508,51.562 h2
  text "'.Print_Time'" at 18.034,51.562 h2
  text ".Layer_Name" at 14.656,-21.806 h1.52
M3 3D STEP Top:
  text ".Layer_Name" at 14.656,-21.806 h1.52
M4 3D STEP Bottom:
  text ".Layer_Name" at 14.656,-21.806 h1.52
M5 Assembly Top:
  lines w0.254: -7.417,-23.626 160.223,-23.626 ; -7.417,-18.462 160.274,-18.462 ; -7.417,-13.297 -7.417,-28.791 94.31,-28.791 160.274,-28.791 160.274,-13.297 -7.404,-13.297 -7.404,-28.791 32.614,-28.791 ; 55.194,-28.791 55.194,-13.297 ; 87.376,-18.462 87.376,-13.297 ; 108.712,-18.462 108.712,-13.297 ; 124.511,-28.956 124.511,-23.804
  text "COMPONENTS MARKED 'DNP' SHOULD NOT BE POPULATED." at 29.299,-8.09 h1.52
  text "ASSEMBLY VARIANT:" at 29.286,-11.024 h1.52
  text ".VariantName" at 55.601,-11.024 h1.52
  text "PCB VIEWED FROM TOP SIDE" at -5.804,-16.654 h1.52
  text "BOARD #:" at 57.099,-16.654 h1.52
  text ".PRJ_Number" at 70.955,-16.654 h1.52
  text "REV:" at 92.405,-16.654 h1.52
  text ".PCB_Rev" at 99.809,-16.654 h1.52
  text "SVN REV:" at 113.69,-16.654 h1.52
  text ".VersionControl_RevNumber" at 126.543,-16.654 h1.52
  text "TID #:" at 57.099,-21.819 h1.52
  text ".TID" at 70.955,-21.819 h1.52
  text "PLOT NAME =" at -5.804,-27.034 h1.52
  text ".plot_File_Name" at 14.656,-27.034 h1.52
  text "GENERATED    :" at 57.15,-27.034 h1.52
  text ".Print_Date" at 79.235,-27.034 h1.52
  text ".Print_Time" at 97.752,-27.034 h1.52
  text "TEXAS INSTRUMENTS" at 129.87,-27.034 h1.52
M6 Assembly Bottom:
  lines w0.254: -7.429,-18.474 160.261,-18.474 ; -7.379,-23.639 160.261,-23.639 ; 28.334,-28.969 28.334,-23.817 ; 44.133,-18.474 44.133,-13.31 ; 65.468,-18.474 65.468,-13.31 ; 97.65,-28.804 97.65,-13.31 ; 120.231,-28.804 160.249,-28.804 160.249,-13.31 -7.429,-13.31 -7.429,-28.804 58.534,-28.804 160.261,-28.804 160.261,-13.31
  text "COMPONENTS MARKED 'DNP' SHOULD NOT BE POPULATED." at 154.991,-8.077 h1.52
  text ".VariantName" at 128.473,-11.024 h1.52
  text "ASSEMBLY VARIANT:" at 154.864,-11.024 h1.52
  text ".VersionControl_RevNumber" at 26.302,-16.667 h1.52
  text "SVN REV:" at 39.154,-16.667 h1.52
  text ".PCB_Rev" at 53.035,-16.667 h1.52
  text "REV:" at 60.439,-16.667 h1.52
  text ".PRJ_Number" at 81.89,-16.667 h1.52
  text "BOARD #:" at 95.745,-16.667 h1.52
  text "PCB VIEWED FROM BOTTOM SIDE" at 158.648,-16.667 h1.52
  text ".TID" at 81.89,-21.831 h1.52
  text "TID #:" at 95.745,-21.831 h1.52
  text "TEXAS INSTRUMENTS" at 22.974,-27.047 h1.52
  text ".Print_Time" at 55.093,-27.047 h1.52
  text ".Print_Date" at 73.609,-27.047 h1.52
  text "GENERATED    :" at 95.694,-27.047 h1.52
  text ".plot_File_Name" at 138.189,-27.047 h1.52
  text "PLOT NAME =" at 158.648,-27.047 h1.52
M9 Title Sheet:
  drawing of 57 lines, arcs and shapes, not listed
  text "1" at 18.792,204.127 h1.78
  text "2" at 82.182,204.127 h1.78
  text "3" at 145.411,204.127 h1.78
  text "4" at 209.08,204.127 h1.78
  text "5" at 272.555,204.127 h1.78
  text "6" at 336.182,204.127 h1.78
  text "A" at -10.579,175.095 h1.78
  text "A" at 365.341,175.095 h1.78
  text "B" at -10.579,114.643 h1.78
  text "B" at 365.341,114.643 h1.78
  text "C" at -10.579,54.318 h1.78
  text "C" at 365.341,54.318 h1.78
  text "PROJECT TITLE:" at 288.125,7.048 h1.14
  text ".PRJ_Title" at 289.395,3.662 h1.78
  text "DESIGNED FOR:" at 288.125,-0.597 h1.14
  text ".PRJ_Customer" at 289.395,-4.153 h1.78
  text "D" at -10.579,-5.88 h1.78
  text "D" at 365.341,-5.88 h1.78
  text "FILE NAME:" at 288.125,-8.217 h1.14
  text ".PCB_File_Name_No_Path" at 289.395,-11.265 h1.78
  text "Texas Instruments (TI) and/or its licensors do not warrant the accuracy or completeness of this specification" at 161.9,-15.376 h1.14
  text "ENGINEER:" at 288.125,-15.583 h1.14
  text "LAYOUT BY:" at 326.352,-15.583 h1.14
  text "or any information contained therein. TI and/or its licensors do not warrant that this design will meet" at 160.757,-18.237 h1.14
  text ".PRJ_Engineer" at 289.395,-19.52 h1.78
  text ".PCB_Layout" at 327.635,-19.52 h1.78
  text "the specifications, will be suitable for your application or fit for any particular purpose, or will operate in" at 160.757,-21.099 h1.14
  text ".Layer_Name" at 14.656,-21.806 h1.52
  text "ALTIUM DESIGNER VERSION:" at 326.352,-23.457 h1.14
  text "an implementation. TI and/or its licensors do not warrant that the design is production worthy. You should" at 160.757,-23.961 h1.14
  text "completely validate and test your design implementation to confirm the system functionality for your application." at 161.9,-26.822 h1.14
  text ".print_Scale" at 289.395,-26.843 h1.78
  text ".Application_BuildNumber" at 327.635,-26.843 h1.78
  text "1" at 18.792,-32.093 h1.78
  text "2" at 82.182,-32.093 h1.78
  text "3" at 145.411,-32.093 h1.78
  text "4" at 209.08,-32.093 h1.78
  text "5" at 272.555,-32.093 h1.78
  text "6" at 336.182,-32.093 h1.78
M10 Fab Notes:
  drawing of 189 lines, arcs and shapes, not listed
  text "DESIGN INFORMATION" at 314.503,161.447 h1.52
  text "MIN. TRACK WIDTH:" at 298.131,158.091 h1.52
  text "8" at 325.976,158.091 h1.52
  text "MIL" at 329.907,158.091 h1.52
  text "MIN. CLEARANCE:" at 298.131,154.938 h1.52
  text "0.2" at 324.452,154.938 h1.52
  text "mm" at 329.907,154.938 h1.52
  text "MIN. VIA PAD SIZE:" at 298.131,151.785 h1.52
  text "24" at 325.214,151.785 h1.52
  text "MIL" at 329.907,151.785 h1.52
  text "0.05mm (2MIL)" at 315.784,148.486 h1.52
  text "MINIMUM ANNULAR RING" at 289.769,148.277 h1.52
  text "EXTERNAL" at 333.768,148.277 h1.52
  text "PER" at 294.849,145.48 h1.52
  text "IPC-D-275 CLASS 2 LEVEL C" at 300.437,145.48 h1.52
  text "MIL, HOLES" at 338.238,142.928 h1.52
  text "+/-" at 328.27,142.709 h1.52
  text "+/-" at 349.961,142.709 h1.52
  text "REGISTRATION TOLERANCES:" at 289.769,142.682 h1.52
  text "METAL" at 320.243,142.682 h1.52
  text "5" at 334.879,142.683 h1.52
  text "3" at 356.037,142.683 h1.52
  text "MIL" at 358.99,142.682 h1.52
  text "HOLE SIZE TOLERANCE (UNLESS OTHERWISE SPECIFIED):" at 289.769,140.185 h1.52
  text "+/-" at 349.961,140.112 h1.52
  text "3" at 356.037,140.085 h1.52
  text "MIL" at 358.99,140.085 h1.52
  text "MATERIAL:" at 287.87,136.589 h1.52
  text "FR-4 High Tg" at 312.926,133.324 h1.52
  text "X" at 309.257,133.122 h1.52
  text "FR-408" at 298.563,133.007 h1.52
  text "OTHER" at 336.358,133.007 h1.52
  text "62 MIL (1.6mm) +/-10%" at 306.694,129.374 h1.52
  text "X" at 303.643,129.312 h1.52
  text "THICKNESS:" at 289.769,129.165 h1.52
  text "OTHER" at 339.33,129.165 h1.52
  text "TOLERANCE:" at 289.769,125.652 h1.52
  text "X" at 311.314,125.652 h1.52
  text "ANSI IPC-6012 TYPE 3 CLASS 2" at 315.836,125.652 h1.52
  text "OTHER +/-" at 315.835,121.989 h1.52
  text "BOW & TWIST:" at 289.769,118.302 h1.52
  text "X" at 311.314,118.302 h1.52
  text "ANSI IPC-6012 TYPE 3 CLASS 2" at 315.836,118.302 h1.52
  text "OTHER +/-" at 315.835,114.576 h1.52
  text "DRILLING:" at 287.87,111.258 h1.52
  text "NC_DRILL FILES" at 332.599,108.586 h1.52
  text "REFERENCE:" at 289.769,108.486 h1.52
  text "X" at 306.463,108.484 h1.52
  text "AS SHOWN" at 310.984,108.486 h1.52
  text "X" at 329.348,108.486 h1.52
  text "OTHER" at 340.168,104.873 h1.52
  text "PTH COPPER THICKNESS:" at 289.761,104.783 h1.52
  text "X" at 318.697,104.783 h1.52
  text "20-30 um" at 321.948,104.783 h1.52
  text "BOARD FINISH:" at 287.87,101.034 h1.52
  text "SILKSCREEN:" at 291.812,98.237 h1.52
  text "X" at 316.14,98.237 h1.52
  text "TOP" at 319.112,98.237 h1.52
  text "X" at 329.094,98.237 h1.52
  text "BOTTOM" at 332.091,98.237 h1.52
  text "SILKSCREEN COLOR:" at 291.812,94.295 h1.52
  text "X" at 316.115,94.295 h1.52
  text "WHITE" at 319.112,94.295 h1.52
  text "OTHER" at 332.091,94.295 h1.52
  text "X" at 319.442,90.652 h1.52
  text "GREEN" at 322.439,90.652 h1.52
  text "OTHER" at 338.136,90.652 h1.52
  text "SOLDER RESIST COLOR:" at 291.812,90.477 h1.52
  text "X" at 319.442,86.734 h1.52
  text "MATTE" at 322.439,86.734 h1.52
  text "SEMI-GLOSS" at 338.125,86.717 h1.52
  text "IMMERSION GOLD (ENIG)" at 314.819,82.345 h1.52
  text "ENEPIG" at 348.793,82.162 h1.52
  text "SURFACE FINISH:" at 287.87,82.136 h1.52
  text "X" at 310.298,82.136 h1.52
  text "IMM. TIN/SILVER OR EQUIV" at 296.24,78.649 h1.52
  text "OTHER" at 332.599,78.549 h1.52
  text "ARRAY/PANEL:" at 287.87,74.602 h1.52
  text "CUT AND TRIM PER M1 BOARD OUTLINE" at 314.819,74.393 h1.52
  text "N.C. ROUTE" at 314.819,70.94 h1.52
  text "X" at 332.295,70.94 h1.52
  text "V. SCORE" at 336.816,70.94 h1.52
  text "CERTIFICATION:" at 287.87,67.66 h1.52
  text "MATERIALS AND WORKMANSHIP FOR ALL PCBS" at 306.285,67.66 h1.52
  text "TO MEET OR EXCEED THE REQUIREMENTS OF:" at 306.285,65.271 h1.52
  text "X" at 297.078,62.003 h1.52
  text "ANSI IPC-A-600F CLASS ->" at 300.329,62.003 h1.52
  text "X" at 342.188,62.003 h1.52
  text "2" at 344.982,62.003 h1.52
  text "1" at 336.981,61.965 h1.52
  text "3" at 353.973,61.965 h1.52
  text "X" at 317.702,58.252 h1.52
  text "RoHS" at 320.953,58.252 h1.52
  text "OTHER" at 337.321,58.252 h1.52
  text "PER ORDER" at 347.407,58.252 h1.52
  text "ALL BOARDS MUST MEET OR EXCEED UL94-V0 REQUIREMENTS." at 288.569,54.345 h1.52
  text "PCB MUST BEAR THE UL94V-0 UL REGISTERED MATERIAL ID NUMBER" at 288.569,51.397 h1.52
  text "ADDITIONAL REQUIREMENTS:" at 287.87,47.094 h1.52
  text "MICROSECTION:" at 289.769,44.373 h1.52
  text "YES" at 312.775,44.373 h1.52
  text "REQUIRED" at 334.657,40.707 h1.52
  text "BARE BOARD ELEC. TEST:" at 289.769,40.634 h1.52
  text "NONE" at 322.935,40.634 h1.52
  text "X" at 331.66,40.634 h1.52
  text "PER ORDER" at 349.693,40.634 h1.52
  text "XX MIL VIAS REQUIRE NON-CONDUCTIVE FILL AND PLANARIZE" at 294.04,35.428 h1.5
  text "XX MIL VIAS REQUIRE CONDUCTIVE FILL AND PLANARIZE" at 294.243,32.787 h1.52
  text "OUTER XX MIL VIAS REQUIRE 50 OHM SINGLE-ENDED IMPEDANCE" at 294.218,28.637 h1.47
  text "LAYER 2 & 3 (INNER LAYERS) XX MIL WIDE, XX MIL SPACE / TRACES REQUIRE 100 OHM DIFFERENTIAL IMPEDANCE" at 294.015,22.65 h1.52
  text ".Layer_Name" at 152.927,8.535 h1.52
  text ".Layer_Name" at 14.656,-21.806 h1.52
M11 Gerber Information:
  lines w0.254: -7.417,-23.626 160.223,-23.626 ; -7.417,-18.462 160.274,-18.462 ; -7.417,-13.297 -7.417,-28.791 94.31,-28.791 160.274,-28.791 160.274,-13.297 -7.404,-13.297 -7.404,-28.791 32.614,-28.791 ; 55.194,-28.791 55.194,-13.297 ; 87.376,-18.462 87.376,-13.297 ; 108.712,-18.462 108.712,-13.297 ; 124.511,-28.956 124.511,-23.804
  text "ALL ARTWORK VIEWED FROM TOP SIDE" at -5.804,-16.654 h1.52
  text "BOARD #:" at 57.099,-16.654 h1.52
  text ".PRJ_Number" at 70.955,-16.654 h1.52
  text "REV:" at 92.405,-16.654 h1.52
  text ".PCB_Rev" at 99.809,-16.654 h1.52
  text "SVN REV:" at 113.69,-16.654 h1.52
  text ".VersionControl_RevNumber" at 126.543,-16.654 h1.52
  text "LAYER NAME =" at -5.804,-21.806 h1.52
  text "TID #:" at 57.099,-21.819 h1.52
  text ".TID" at 70.955,-21.819 h1.52
  text "PLOT NAME =" at -5.804,-27.034 h1.52
  text ".plot_File_Name" at 14.656,-27.034 h1.52
  text "GENERATED    :" at 57.15,-27.034 h1.52
  text ".Print_Date" at 79.235,-27.034 h1.52
  text ".Print_Time" at 97.752,-27.034 h1.52
  text "TEXAS INSTRUMENTS" at 129.87,-27.034 h1.52
M12 Stackup:
  drawing of 191 lines, arcs and shapes, not listed
  text "Layer" at 248.865,198.882 h1.52
  text "Name" at 259.277,198.882 h1.52
  text "Material" at 282.892,198.882 h1.52
  text "Thickness" at 304.731,198.882 h1.52
  text "Constant" at 321.236,198.882 h1.52
  text "Board Layer Stack" at 335.711,198.882 h1.52
  text "1" at 248.865,195.834 h1.52
  text "Top Overlay" at 259.277,195.834 h1.52
  text "2" at 248.865,192.786 h1.52
  text "Top Solder" at 259.277,192.786 h1.52
  text "Solder Resist" at 282.892,192.786 h1.52
  text "0.40mil" at 304.731,192.786 h1.52
  text "3.5" at 321.236,192.786 h1.52
  text "3" at 248.865,189.738 h1.52
  text "Top Layer" at 259.277,189.738 h1.52
  text "Copper" at 282.892,189.738 h1.52
  text "1.40mil" at 304.731,189.738 h1.52
  text "4" at 248.865,186.69 h1.52
  text "Dielectric1" at 259.277,186.69 h1.52
  text "FR-4" at 282.892,186.69 h1.52
  text "59.20mil" at 304.731,186.69 h1.52
  text "4.8" at 321.236,186.69 h1.52
  text "5" at 248.865,183.642 h1.52
  text "Bottom Layer" at 259.277,183.642 h1.52
  text "Copper" at 282.892,183.642 h1.52
  text "1.40mil" at 304.731,183.642 h1.52
  text "6" at 248.865,180.594 h1.52
  text "Bottom Solder" at 259.277,180.594 h1.52
  text "Solder Resist" at 282.892,180.594 h1.52
  text "0.40mil" at 304.731,180.594 h1.52
  text "3.5" at 321.236,180.594 h1.52
  text "7" at 248.865,177.546 h1.52
  text "Bottom Overlay" at 259.277,177.546 h1.52
  text ".Layer_Name" at 14.656,-21.806 h1.52
M13 Component Bodies Top:
  text ".Layer_Name" at 14.656,-21.806 h1.52
M14 Component Bodies Bottom:
  text ".Layer_Name" at 14.656,-21.806 h1.52
M15 Courtyards Top:
  text ".Layer_Name" at 14.656,-21.806 h1.52
M16 Courtyards Bottom:
  text ".Layer_Name" at 14.656,-21.806 h1.52
Drill Drawing:
  circle w0.254: c136.241,73.47 r0.703
  lines w0.254: 135.538,75.929 136.944,75.929 136.944,77.335 135.538,77.335 135.538,75.929 ; 135.538,79.092 136.241,79.443 136.944,79.092 136.593,79.795 136.944,80.497 136.241,80.146 135.538,80.497 135.89,79.795 135.538,79.092 ; 135.538,82.605 135.89,82.605 136.241,82.254 136.593,82.605 136.944,82.605 136.593,82.957 136.944,83.308 136.593,83.308 136.241,83.66 135.89,83.308 135.538,83.308 135.89,82.957 135.538,82.605
  lines w0.305: 134.264,71.819 216.362,71.819 ; 134.264,84.468 216.362,84.468 ; 142.85,68.656 142.85,87.63 ; 151.287,68.656 151.287,87.63 ; 167.453,68.656 167.453,87.63 ; 174.037,68.656 174.037,87.63 ; 183.568,68.656 183.568,87.63 ; 201.972,68.656 201.972,87.63 ; 134.264,68.656 216.362,68.656 216.362,87.63 134.264,87.63 134.264,68.656
  text "Symbol" at 136.162,85.416 h1.83
  text "Quantity" at 143.799,85.416 h1.83
  text "Finished Hole Size" at 152.235,85.416 h1.83
  text "Plated" at 168.402,85.416 h1.83
  text "Hole Type" at 174.986,85.416 h1.83
  text "Drill Layer Pair" at 184.517,85.416 h1.83
  text "Hole Tolerance" at 202.92,85.416 h1.83
  text "7" at 143.799,82.254 h1.52
  text "11.81mil (0.300mm)" at 152.235,82.254 h1.52
  text "PTH" at 168.402,82.254 h1.52
  text "Round" at 174.986,82.254 h1.52
  text "Top Layer - Bottom Layer" at 184.517,82.254 h1.52
  text "7" at 143.799,79.092 h1.52
  text "19.69mil (0.500mm)" at 152.235,79.092 h1.52
  text "PTH" at 168.402,79.092 h1.52
  text "Round" at 174.986,79.092 h1.52
  text "Top Layer - Bottom Layer" at 184.517,79.092 h1.52
  text "9" at 143.799,75.929 h1.52
  text "40.00mil (1.016mm)" at 152.235,75.929 h1.52
  text "PTH" at 168.402,75.929 h1.52
  text "Round" at 174.986,75.929 h1.52
  text "Top Layer - Bottom Layer" at 184.517,75.929 h1.52
  text "6" at 143.799,72.767 h1.52
  text "98.43mil (2.500mm)" at 152.235,72.767 h1.52
  text "PTH" at 168.402,72.767 h1.52
  text "Round" at 174.986,72.767 h1.52
  text "Top Layer - Bottom Layer" at 184.517,72.767 h1.52
  text "29 Total" at 143.799,69.605 h1.52
  text ".Layer_Name" at 14.656,-21.806 h1.52
M17 Embedded Cavity:
  text ".Layer_Name" at 14.656,-21.806 h1.52
M18 Embedded Assembly:
  text ".Layer_Name" at 14.656,-21.806 h1.52
M19 Embedded Keepout:
  text ".Layer_Name" at 14.656,-21.806 h1.52

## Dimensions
0,-10.16 to 25.4,-10.16 on M2 Board Dimensions
0,0 to 0,50.8 on M2 Board Dimensions
0,0 to 38.1,0 on M2 Board Dimensions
